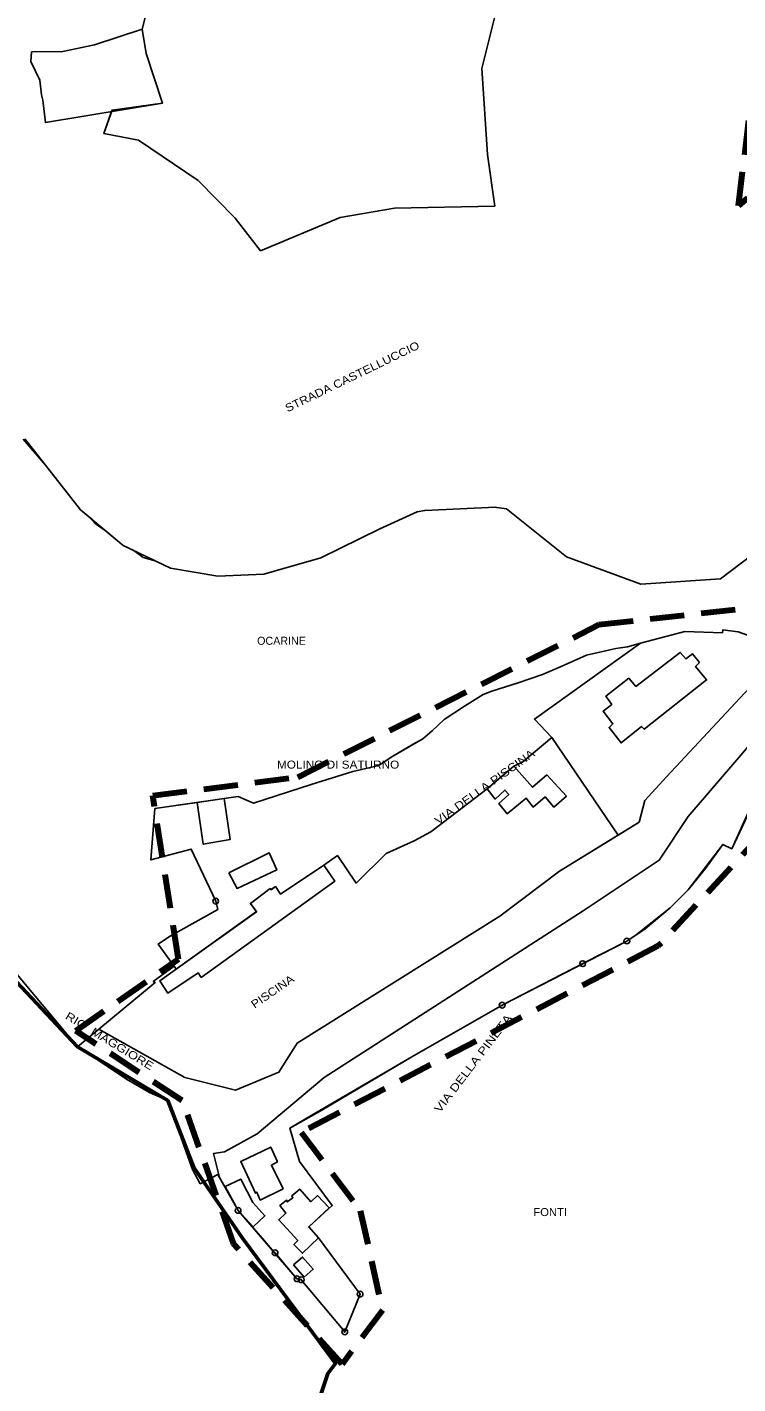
# Model space of a CAD drawing. Extents: x 654952 to 658955, y 890426 to 894481.
# Drawn here: x 657509.1 to 657758, y 890673.7 to 891148.5 of the extents above; entities that cross this region are included whole.
import ezdxf

# ---------------------------------------------------------------- set-up
doc = ezdxf.new("R2010")
doc.units = 0
doc.header["$LTSCALE"] = 4
doc.header["$PDMODE"] = 32
doc.header["$PDSIZE"] = 2
doc.linetypes.add('MEDIUM_DASHED', pattern=[4.5, 3, -1.5])
for name, color, linetype, lineweight in [('1', 7, 'Continuous', 25), ('2', 7, 'Continuous', 25), ('35', 7, 'Continuous', 25), ('36', 7, 'Continuous', 25), ('37', 7, 'Continuous', 25), ('4', 7, 'Continuous', 25), ('56', 7, 'Continuous', 25), ('59', 7, 'Continuous', 53), ('7', 7, 'MEDIUM_DASHED', 100)]:
    doc.layers.add(name, color=color, linetype=linetype, lineweight=lineweight)
doc.layers.add('58', color=7, linetype='Continuous')

msp = doc.modelspace()

# ---------------------------------------------------------------- linework, layer by layer
at = {"layer": '1'}
for p, q in [((657634.88, 890859.27), (657644.59, 890863.75)), ((657703.64, 890820.73), (657719.11, 890828.65)), ((657719.11, 890828.65), (657722.39, 890830.85)), ((657675.45, 890806.2), (657703.64, 890820.73)), ((657595.92, 890719.53), (657603.6, 890710.43)), ((657603.6, 890710.43), (657605.1, 890710.09)), ((657620.34, 890691.85), (657625.69, 890705.09))]:
    msp.add_line(p, q, dxfattribs=at)
for points in [[(657758.11, 890936.83), (657752.75, 890937.58), (657752.55, 890936.55), (657739.37, 890936.96), (657723.91, 890932.87), (657719.39, 890931.67), (657715.28, 890930.99), (657704.94, 890928.67), (657696.14, 890924.76), (657689.54, 890921.93), (657681.04, 890919.02), (657671.8, 890916.16), (657668.82, 890914.96), (657662.25, 890910.85), (657655.19, 890906.18), (657650.95, 890902.25), (657647.69, 890899.38), (657644.23, 890897.5), (657636.61, 890893.01), (657632.3, 890890.06), (657623.12, 890888.03), (657608.6, 890883.4), (657588.38, 890876.91), (657583.03, 890879.21), (657553.87, 890875.05), (657552.39, 890857.02), (657566.58, 890860.86), (657575.13, 890842.61), (657575.9, 890839.73), (657558.92, 890830.2), (657555.04, 890827.56), (657560.62, 890819.8), (657553.26, 890814.5), (657553.98, 890814.13), (657526.68, 890791.63), (657534.7, 890786.51), (657543.89, 890780.35), (657551.97, 890775.68), (657558.34, 890772.82), (657566.96, 890748.65), (657569.73, 890743.7), (657575.84, 890746.98), (657582.96, 890734.36)], [(657725.36, 890877.89), (657732.97, 890886.13), (657768.49, 890924.18), (657782.81, 890935.06), (657779.02, 890940.19), (657767.79, 890933.42), (657764.28, 890934.69), (657763.67, 890934.84)], [(657763.67, 890934.84), (657758.11, 890936.83), (657752.75, 890937.58), (657752.55, 890936.55)], [(657723.91, 890932.87), (657719.39, 890931.67), (657715.28, 890930.99), (657704.94, 890928.67), (657696.14, 890924.76), (657689.54, 890921.93), (657681.04, 890919.02), (657671.8, 890916.16), (657668.82, 890914.96), (657662.25, 890910.85), (657655.19, 890906.18), (657650.95, 890902.25), (657647.69, 890899.38), (657644.23, 890897.5), (657636.61, 890893.01), (657632.3, 890890.06), (657623.12, 890888.03), (657608.6, 890883.4), (657588.38, 890876.91), (657583.03, 890879.21), (657578.12, 890878.51), (657568.65, 890877.16)], [(657574.37, 890754.32), (657578.26, 890754.88), (657589.68, 890761.22), (657613.14, 890780.87), (657703.81, 890839.21), (657730.45, 890856.96), (657740.58, 890872.18), (657758.97, 890893.74), (657776.73, 890914.66), (657786.02, 890929.14), (657786.92, 890929.49), (657782.81, 890935.06)], [(657752.55, 890936.55), (657739.37, 890936.96), (657723.91, 890932.87), (657686.76, 890906.32), (657692.81, 890899.83), (657716.05, 890865.73)], [(657692.81, 890899.83), (657686.76, 890906.32), (657723.91, 890932.87)], [(657782.81, 890935.06), (657768.49, 890924.18), (657732.97, 890886.13), (657725.36, 890877.89)], [(657786.92, 890929.49), (657786.02, 890929.14), (657776.73, 890914.66), (657758.97, 890893.74), (657740.58, 890872.18), (657730.45, 890856.96), (657703.81, 890839.21), (657613.14, 890780.87), (657589.68, 890761.22), (657578.26, 890754.88), (657574.37, 890754.32), (657576.43, 890745.94), (657582.96, 890734.36), (657592.26, 890723.72)], [(657722.39, 890830.85), (657734.26, 890840.22), (657740.54, 890846.62), (657752.72, 890862.46), (657755.86, 890860.94), (657761.88, 890874.11), (657766.09, 890882.69), (657768.92, 890889.28), (657771.75, 890894.27), (657775.9, 890899.63), (657781.51, 890904.42), (657793.93, 890915.04)], [(657719.11, 890828.65), (657725.5, 890832.95), (657734.26, 890840.22), (657740.54, 890846.62), (657746.63, 890853.99), (657752.72, 890862.46), (657755.86, 890860.94), (657761.88, 890874.11), (657766.09, 890882.69), (657768.92, 890889.28), (657771.75, 890894.27), (657775.9, 890899.63), (657781.51, 890904.42)], [(657644.59, 890863.75), (657650.52, 890866.86), (657670.25, 890881.87), (657679.56, 890889.84), (657682.69, 890891.33), (657692.81, 890899.83)], [(657692.81, 890899.83), (657682.69, 890891.33), (657679.56, 890889.84), (657670.25, 890881.87)], [(657692.81, 890899.83), (657716.05, 890865.73), (657692.81, 890899.83)], [(657670.25, 890881.87), (657650.52, 890866.86), (657644.59, 890863.75), (657634.88, 890859.27), (657624.28, 890848.96), (657617.76, 890858.58), (657612.95, 890855.24)], [(657568.65, 890877.16), (657553.87, 890875.05), (657552.39, 890857.02), (657566.58, 890860.86), (657575.13, 890842.61), (657575.9, 890839.73), (657558.92, 890830.2), (657555.04, 890827.56), (657560.62, 890819.8)], [(657725.36, 890877.89), (657723.46, 890870.28), (657695.57, 890853.16), (657674.64, 890837.3)], [(657716.05, 890865.73), (657723.46, 890870.28), (657725.36, 890877.89)], [(657674.64, 890837.3), (657695.57, 890853.16), (657716.05, 890865.73)], [(657612.95, 890855.24), (657617.76, 890858.58), (657624.28, 890848.96), (657634.88, 890859.27)], [(657612.95, 890855.24), (657597.87, 890845.04), (657596.08, 890847.72), (657594.57, 890846.58), (657594.21, 890846.98), (657587.27, 890841.8)], [(657596.08, 890847.72), (657597.87, 890845.04), (657612.95, 890855.24)], [(657587.27, 890841.8), (657594.21, 890846.98), (657594.57, 890846.58), (657596.08, 890847.72)], [(657674.64, 890837.3), (657603.62, 890792.92), (657597.29, 890782.77), (657582.07, 890776.43), (657564.31, 890780.87), (657534.15, 890797.79), (657526.68, 890791.63)], [(657534.15, 890797.79), (657564.31, 890780.87), (657582.07, 890776.43), (657597.29, 890782.77), (657603.62, 890792.92), (657674.64, 890837.3)], [(657560.62, 890819.8), (657561.33, 890818.81), (657589.42, 890838.92), (657587.27, 890841.8)], [(657587.27, 890841.8), (657589.42, 890838.92), (657561.33, 890818.81), (657560.62, 890819.8)], [(657560.62, 890819.8), (657553.26, 890814.5), (657553.98, 890814.13), (657534.15, 890797.79)], [(657625.69, 890705.09), (657611.11, 890724.82), (657607.73, 890728.66), (657615.95, 890736.14), (657604.49, 890751.43), (657601.11, 890763.19), (657612.35, 890769.42), (657643.84, 890788.11), (657675.45, 890806.2)], [(657526.68, 890791.63), (657558.34, 890772.82), (657567.52, 890749.43), (657570.99, 890744.37)], [(657611.11, 890724.82), (657607.73, 890728.66), (657615.95, 890736.14), (657604.49, 890751.43), (657601.11, 890763.19), (657608.78, 890767.65), (657643.84, 890788.11)], [(657570.99, 890744.37), (657575.84, 890746.98), (657576.43, 890745.94), (657574.37, 890754.32)], [(657592.26, 890723.72), (657603.6, 890710.43), (657605.1, 890710.09), (657620.34, 890691.85), (657625.69, 890705.09)]]:
    msp.add_lwpolyline(points, dxfattribs=at)
for p in [(657719.11, 890828.65), (657703.64, 890820.73), (657675.45, 890806.2), (657582.96, 890734.36), (657595.92, 890719.53), (657603.6, 890710.43), (657605.1, 890710.09), (657625.69, 890705.09), (657620.34, 890691.85)]:
    msp.add_point(p, dxfattribs=at)
at = {"layer": '2'}
msp.add_lwpolyline([(657510.62, 891139.83), (657510.43, 891136.48), (657513.49, 891129.99), (657514.09, 891124.83), (657514.58, 891122.91), (657515.48, 891115.1), (657556.51, 891121.91), (657550.75, 891139.24), (657549.42, 891147.77), (657532.71, 891142.35), (657521.56, 891140.02)], close=True, dxfattribs=at)
at = {"layer": '35'}
msp.add_lwpolyline([(657766.09, 890882.69), (657755.86, 890860.94), (657752.72, 890862.46), (657740.54, 890846.62), (657734.26, 890840.22), (657722.39, 890830.85), (657719.11, 890828.65), (657675.45, 890806.2), (657643.84, 890788.11), (657612.35, 890769.42), (657601.11, 890763.19), (657604.49, 890751.43), (657615.95, 890736.14), (657607.73, 890728.66), (657611.11, 890724.82), (657625.69, 890705.09), (657620.34, 890691.85), (657605.1, 890710.09), (657603.6, 890710.43), (657582.96, 890734.36), (657575.84, 890746.98), (657570.99, 890744.37), (657584.57, 890724.61), (657617.13, 890680.78), (657614.42, 890677.28), (657594.65, 890616.78)], dxfattribs=at)
at = {"layer": '36'}
for points in [[(657377.51, 891314.8), (657394.7, 891315.26), (657416.2, 891306.19), (657427, 891299.44), (657437.44, 891290.85), (657445.83, 891284.61), (657453.28, 891280.86), (657469.29, 891273.97), (657494.54, 891261.55), (657501.86, 891257.22), (657519.04, 891246.41), (657529.74, 891236.81), (657541.76, 891219.19), (657547.47, 891207.4), (657552.96, 891185.3), (657552.92, 891161.84), (657549.42, 891147.77), (657550.75, 891139.24), (657556.51, 891121.91), (657538.66, 891118.94)], [(657538.66, 891118.94), (657535.96, 891111.27), (657548.07, 891109), (657569.02, 891094.82), (657581.96, 891081.61), (657590.87, 891070.28), (657618.73, 891081.89), (657637.72, 891085.14), (657672.85, 891085.89), (657670.36, 891103.93), (657668.28, 891134.03), (657674.22, 891157.35), (657683.59, 891178.05), (657695.83, 891188.86), (657694.99, 891192.51), (657701.57, 891221.76), (657717.86, 891252.48), (657747.12, 891269.62), (657772.31, 891278.75), (657738.71, 891281.98), (657700.64, 891287.28), (657666.91, 891290.65), (657631.96, 891282.25)]]:
    msp.add_lwpolyline(points, dxfattribs=at)
at = {"layer": '37'}
for points in [[(657531.59, 890976.41), (657527.82, 890979.57), (657515.55, 890995.16), (657507.76, 891004.26)], [(657788.94, 891005.23), (657784.23, 890979.95), (657751.92, 890955.43), (657723.95, 890953.61), (657697.94, 890963.11), (657676.93, 890979.92), (657673.58, 890980.35), (657673.12, 890980.45), (657648.33, 890979.38), (657645.71, 890978.83), (657632.58, 890972.94), (657612, 890962.82), (657592, 890957.09), (657575.89, 890956.36), (657559.28, 890959.19), (657553.93, 890961.73), (657549.79, 890962.92), (657546.41, 890965.3)], [(657546.41, 890965.3), (657542.74, 890967.04), (657536.38, 890972.38), (657532.97, 890974.79), (657531.59, 890976.41)], [(657723.91, 890932.87), (657739.37, 890936.96), (657752.55, 890936.55), (657752.75, 890937.58), (657758.11, 890936.83), (657767.79, 890933.42), (657779.02, 890940.19)], [(657588.38, 890876.91), (657608.6, 890883.4), (657623.12, 890888.03), (657632.3, 890890.06), (657636.61, 890893.01), (657647.69, 890899.38), (657650.95, 890902.25), (657655.19, 890906.18), (657662.25, 890910.85), (657668.82, 890914.96), (657671.8, 890916.16), (657681.04, 890919.02), (657689.54, 890921.93), (657696.14, 890924.76), (657704.94, 890928.67), (657715.28, 890930.99), (657719.39, 890931.67), (657723.91, 890932.87)], [(657575.13, 890842.61), (657566.58, 890860.86), (657552.39, 890857.02), (657553.87, 890875.05), (657583.03, 890879.21), (657588.38, 890876.91)], [(657553.98, 890814.13), (657553.26, 890814.5), (657560.62, 890819.8), (657555.04, 890827.56), (657558.92, 890830.2), (657575.9, 890839.73), (657575.13, 890842.61)], [(657502.58, 890820.53), (657526.68, 890791.63), (657553.98, 890814.13)]]:
    msp.add_lwpolyline(points, dxfattribs=at)
msp.add_point((657575.13, 890842.61), dxfattribs=at)
at = {"layer": '4'}
for points in [[(657744.6, 890926.08), (657743.15, 890924.7), (657747.02, 890920.02), (657725.19, 890902.8), (657724.19, 890903.74), (657717.1, 890898), (657712.89, 890903.44), (657714.25, 890904.72), (657710.8, 890909.1), (657713.84, 890911.46), (657711.76, 890914.32), (657719.79, 890920.62), (657722.29, 890917.76), (657737.81, 890929.66), (657739.78, 890927.42), (657742.12, 890929.12)], [(657691.07, 890886.82), (657697.97, 890879.36), (657693.51, 890875.52), (657690.47, 890879.12), (657686.34, 890875.56), (657683.8, 890878.68), (657677.25, 890873.22), (657674.3, 890876.82), (657677.73, 890879.94), (657676.42, 890881.5), (657672.94, 890878.36), (657670.21, 890881.92), (657673.63, 890884.82), (657679.56, 890889.84), (657686.12, 890882.46)], [(657568.65, 890877.16), (657570.76, 890862.53), (657580.25, 890864.2), (657578.12, 890878.51)], [(657579.69, 890852.48), (657593.9, 890859.56), (657596.52, 890853.54), (657582.63, 890847.06)], [(657612.95, 890855.24), (657616.87, 890849.62), (657570.1, 890815.94), (657568.94, 890817.5), (657558.35, 890810.46), (657555.56, 890814.74), (657589.4, 890838.98), (657587.27, 890841.8), (657594.21, 890846.98), (657594.55, 890846.64), (657596.08, 890847.72), (657597.85, 890845.1)], [(657598.77, 890741.93), (657590.75, 890737.99), (657589.58, 890740.7), (657589.08, 890740.37), (657583.93, 890751.5), (657594.41, 890756.51), (657596.74, 890751.33), (657594.64, 890750.23)], [(657578.43, 890742.78), (657583.9, 890745.34), (657588.08, 890737.1), (657592.38, 890732.47), (657588.24, 890728.63), (657582.96, 890734.36)], [(657614.81, 890735.25), (657610.79, 890739.56), (657608.48, 890737.41), (657604.54, 890741.77), (657601.74, 890739.43), (657602.19, 890738.82), (657600.18, 890737.34), (657599.95, 890737.95), (657597.64, 890736.04), (657599.73, 890733.39), (657597.23, 890731.05), (657603.89, 890723.84), (657602.52, 890722.44), (657605.58, 890719.35), (657611.11, 890724.82), (657607.73, 890728.66)], [(657602.42, 890715.32), (657605.55, 890718.01), (657609.32, 890713.8), (657606.16, 890711.02)]]:
    msp.add_lwpolyline(points, close=True, dxfattribs=at)
at = {"layer": '56'}
for points in [[(657674.22, 891157.35), (657668.28, 891134.03), (657670.36, 891103.93), (657672.85, 891085.89), (657637.72, 891085.14), (657618.73, 891081.89), (657590.87, 891070.28), (657581.96, 891081.61), (657569.02, 891094.82), (657548.07, 891109), (657535.96, 891111.27), (657538.85, 891119.51), (657556.51, 891121.91), (657550.75, 891139.24), (657549.42, 891147.77), (657552.92, 891161.84)], [(657508.28, 891004.39), (657527.82, 890979.57), (657542.74, 890967.04), (657559.28, 890959.19), (657575.89, 890956.36), (657592, 890957.09), (657612, 890962.82), (657632.58, 890972.94), (657645.71, 890978.83), (657648.33, 890979.38), (657673.12, 890980.45), (657673.58, 890980.35), (657676.93, 890979.92), (657697.94, 890963.11), (657723.95, 890953.61), (657751.92, 890955.43), (657784.23, 890979.95)]]:
    msp.add_lwpolyline(points, dxfattribs=at)
at = {"layer": '59'}
msp.add_lwpolyline([(658193.76, 890651.87), (658064.38, 890699.85), (658064.38, 890699.85), (657974.41, 890701.09), (657969.14, 890700.78), (657969.14, 890700.78), (657825.69, 890625.28), (657729.93, 890574.87), (657713.55, 890566.25), (657677.67, 890578.03), (657652.32, 890587.93), (657597.36, 890612.12), (657594.65, 890616.78), (657604.34, 890647.03), (657614.42, 890677.28), (657617.13, 890680.77), (657584.57, 890724.6), (657567.52, 890749.43), (657558.34, 890772.82), (657526.68, 890791.63), (657492.71, 890827.78)], dxfattribs=at)
at = {"layer": '7'}
msp.add_lwpolyline([(658184.33, 890889.29), (658123.56, 891003.8), (657984.81, 890972.39), (657924.04, 891001.78), (657867.48, 890983.79), (657828.91, 890933.62), (657730.13, 890826.94), (657605.09, 890761.67), (657625.78, 890734.22), (657633.49, 890699.48), (657619.39, 890680.55), (657581.42, 890722.64), (657563.43, 890772.81), (657526.14, 890797.25), (657562.14, 890822.34), (657553.14, 890879.58), (657603.92, 890886.02), (657709.35, 890939.4), (657787.21, 890948.05), (657815.02, 890978.31), (657798.98, 891039.09), (657789.02, 891111.62), (657758.18, 891086.01), (657767.85, 891164.67)], dxfattribs=at)

# ---------------------------------------------------------------- texts
at = {"layer": '58'}
for s, height, rotation, width, p in [('STRADA CASTELLUCCIO', 2.799, 25.814, 1.15, (657600.29, 891013.68)), ('VIA DELLA PISCINA', 2.799, 35.686, 1.2, (657653.08, 890869.19)), ('PISCINA', 2.798, 34.533, 1.15, (657588.73, 890804.95)), ('RIO  MAGGIORE', 2.801, 328.748, 1.2, (657522.2, 890801.6)), ('VIA DELLA PINETA', 2.801, 52.651, 1.25, (657653.67, 890768.32))]:
    msp.add_text(s, height=height, rotation=rotation, dxfattribs=dict(at, width=width)).set_placement(p)
msp.add_text('OCARINE', height=2.801, dxfattribs=at).set_placement((657589.64, 890932.34))
for s, width, p in [('MOLINO DI SATURNO', 1.1, (657596.59, 890889)), ('FONTI', 1.05, (657686.36, 890732.38))]:
    msp.add_text(s, height=2.801, dxfattribs=dict(at, width=width)).set_placement(p)

doc.saveas('drawing.dxf')
